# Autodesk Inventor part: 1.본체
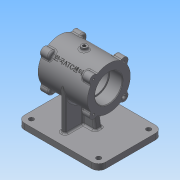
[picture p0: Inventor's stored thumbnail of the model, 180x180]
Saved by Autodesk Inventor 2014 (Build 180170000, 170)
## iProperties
Created: 2016-01
Part Number: 1.본체
Material: Generic
Document SubType Name: Modeling
Designer: Administrator
Density: 1 g/cm^3
Appearance: Default
Author: Administrator
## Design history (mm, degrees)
sketch "스케치1"
  geometry: L1 (-70, 55)-(70, 55); L2 (70, 55)-(70, -55); L3 (70, -55)-(-70, -55); L4 (-70, -55)-(-70, 55); L5 (-70, 55)-(70, -55); L6 (70, 55)-(-70, -55); 1 further point
  constraints: 12 end point, 2 midpoint, 2 parallel, 1 horizontal, 1 perpendicular
  dimensions: "d0" = 140 distance between parallel lines of L2 L4; "d1" = 110 distance between parallel lines of L3 L1
extrude "돌출1" new body sketch "스케치1" distance "d2" = 10; taper "d3" = 0 deg
node "작업 평면1"
sketch "스케치2"
  geometry: L1 (0, 110)-(0, 0) reference; C1 r 37 at (-80, 55); 2 further points
  constraints: 1 centre point, 1 horizontal alignment, 1 midpoint
  dimensions: "d5" = 80 distance from line of L1 C1.centre; "d6" = 74 diameter of C1
extrude "돌출2" join sketch "스케치2" stored distance "d7" = 85; taper "d8" = 0 deg
node "작업 평면2"
sketch "스케치3"
  geometry: L1 (80, -55)-(80, 55) reference; L2 (80, -55)-(70, -55) reference; L3 (70, 55)-(70, -55) reference; L4 (80, 55)-(70, 55) reference; L5 (0, -37)-(70, -37); L6 (0, 37)-(70, 37); A1 r 37 centre (0, 0) between (0, -37) and (0, 37) reference; 1 further point
  constraints: 4 end point, 2 horizontal, 2 point on circle, 2 point on line, 2 tangent
extrude "돌출3" join sketch "스케치3" stored distance "d10" = 8; taper "d11" = 0 deg
node "작업 평면3"
sketch "스케치4"
  geometry: L1 (-70, 0)-(70, 0) reference; L2 (-70, 0)-(-70, 10) reference; L3 (70, 10)-(-70, 10) reference; L4 (70, 0)-(70, 10) reference; L5 (14, 80)-(14, 80) reference; L6 (14, 80)-(6, 80) reference; L7 (6, 80)-(6, 80) reference; L8 (14, 80)-(6, 80) reference; L9 (52.5, 43)-(52.5, 117) reference; L10 (-32.5, 117)-(-32.5, 43) reference; L11 (-9.782, 42.948)-(-15, 10); L12 (29.782, 42.948)-(35, 10); L13 (6, 10)-(14, 10) reference; L14 (6, 80)-(6, 10) reference; L15 (14, 80)-(6, 80) reference; L16 (14, 10)-(14, 80) reference; L17 (-9.782, 42.948)-(-6.179, 65.693); L18 (29.782, 42.948)-(26.179, 65.693); L19 (26.179, 65.693)-(-6.179, 65.693); 3 further points
  constraints: 10 end point, 2 collinear, 2 midpoint, 2 point on line, 1 equal length, 1 horizontal, 1 vertical alignment
  dimensions: "d13" = 99 deg angle of L3 L11; "d14" = 99 deg angle of L3 L12; "d18" = 25 distance of point (10, 10) L11.end; "d19" = 25 distance of point (10, 10) L12.end; "d20" = 32.35825 distance of L18.end L17.end
extrude "돌출4" join sketch "스케치4" stored distance "d21" = 12; taper "d22" = 0 deg
node "작업 평면4"
sketch "스케치6"
  geometry: C1 r 37 at (0, 0) reference; C2 r 23.5 at (0, 0); 1 further point
  constraints: 1 centre point, 1 coincident
  dimensions: "d24" = 47 diameter of C2
extrude "돌출5" cut sketch "스케치6" distance "d25" = 22; taper "d26" = 0 deg
sketch "스케치7"
  geometry: C1 r 21 at (0, 0); C2 r 37 at (0, 0) reference; 1 further point
  constraints: 1 centre point, 1 coincident, 1 horizontal alignment
  dimensions: "d27" = 42 diameter of C1
extrude "돌출6" cut sketch "스케치7" distance "d28" = 41; taper "d29" = 0 deg
node "작업 평면5"
sketch "스케치8"
  geometry: C1 r 37 at (0, 0) reference; C2 r 23.5 at (0, 0); 1 further point
  constraints: 1 centre point, 1 coincident
  dimensions: "d31" = 47 diameter of C2
extrude "돌출7" cut sketch "스케치8" distance "d32" = 22; taper "d33" = 0 deg
node "작업 평면6"
sketch "스케치9"
  geometry: L1 (32.5, -37)-(32.5, 37) reference; L2 (-52.5, 37)-(32.5, 37) reference; L3 (-52.5, 37)-(-52.5, -37) reference; L4 (-52.5, -37)-(32.5, -37) reference; C1 r 5 at (-10, 0); 2 further points
  constraints: 1 centre point, 1 horizontal alignment, 1 midpoint
  dimensions: "d35" = 42.5 distance from line of C1.centre L3; "d36" = 10 diameter of C1
extrude "돌출8" join sketch "스케치9" stored distance "d37" = 22; taper "d38" = 0 deg
sketch "스케치10"
  geometry: L1 (-52.5, 37)-(-52.5, -37) reference; 1 further point
hole "구멍1" diameter "d42" = 5.188; stored, may be unused: countersink angle "d46" = 90 deg, drill point angle "d48" = 0 deg; dims "d40" = 10, "d41" = 10, "d43" = 10, "d44" = 10, "d45" = 2, "d47" = 8
sketch "스케치11"
  geometry: C1 r 23.5 at (0, 0) reference; C2 r 7 at (-26.163, -26.163); C3 r 7 at (-26.163, 26.163); C4 r 7 at (26.163, -26.163); C5 r 7 at (26.163, 26.163); A1 r 37 centre (0, 0) between (-26.163, -26.163) and (-26.163, 26.163) reference; A2 r 37 centre (0, 0) between (-26.163, -26.163) and (-26.163, 26.163); 2 further points
  constraints: 8 point on circle, 5 centre point, 4 equal radius, 2 coincident, 2 horizontal alignment, 2 vertical alignment
  dimensions: "d49" = 7 radius of C3; "d50" = 90 deg dimension on C1.centre C3.centre C2.centre
extrude "돌출9" join sketch "스케치11" distance "d51" = 15; taper "d52" = 0 deg
sketch "스케치12"
  geometry: A1 r 7 centre (-106.163, 81.163) between (-100.767, 85.622) and (-110.622, 75.767) reference; A2 r 7 centre (-106.163, 28.837) between (-110.622, 34.233) and (-100.767, 24.378) reference; A3 r 7 centre (-53.837, 28.837) between (-59.233, 24.378) and (-49.378, 34.233) reference; A4 r 7 centre (-53.837, 81.163) between (-49.378, 75.767) and (-59.233, 85.622) reference; 5 further points
  constraints: 4 coincident
hole "구멍2" sketch "스케치12" at (-106.163, 81.163), (-106.163, 28.837), (-53.837, 28.837), (-53.837, 81.163) diameter "d53" = 3.242; stored, may be unused: countersink angle "d57" = 90 deg, drill point angle "d59" = 118 deg; dims "d54" = 9, "d55" = 10, "d56" = 2, "d58" = 11
node "작업 평면7"
sketch "스케치13"
  geometry: L1 (70, 55)-(-70, 55) reference; L2 (-70, 55)-(-70, -55) reference; L3 (-58, 43)-(58, 43); L4 (58, 43)-(58, -43); L5 (58, -43)-(-58, -43); L6 (-58, -43)-(-58, 43); 5 further points
  constraints: 8 end point, 4 coincident, 2 parallel, 1 horizontal, 1 perpendicular
  dimensions: "d61" = 86 distance between parallel lines of L5 L3; "d62" = 116 distance between parallel lines of L4 L6; "d63" = 12 distance from line of point (-58, 43) L1; "d64" = 12 distance from line of L2 point (-58, 43)
hole "구멍3" sketch "스케치13" at (-58, 43), (58, 43), (-58, -43), (58, -43) diameter "d65" = 8; stored, may be unused: countersink angle "d69" = 90 deg, drill point angle "d71" = 118 deg; dims "d66" = 9, "d67" = 10, "d68" = 2, "d70" = 11
sketch "스케치14"
  geometry: L1 (70, 55)-(-70, 55) reference; L2 (70, -55)-(70, 55) reference; L3 (-35, 40)-(38.226, 40); L4 (55, 23.226)-(55, -23.226); L5 (38.226, -40)-(-38.226, -40); L6 (-55, -23.226)-(-55, 23.226); L7 (-55, 40)-(55, -40); L8 (55, 40)-(-55, -40); C1 r 4 at (58, -43) reference; C2 r 4 at (58, 43) reference; C3 r 4 at (-58, 43) reference; C4 r 4 at (-58, -43) reference; A1 r 20 centre (-58, -43) between (-38.226, -40) and (-55, -23.226); A2 r 20 centre (58, -43) between (55, -23.226) and (38.226, -40); A3 r 20 centre (58, 43) between (38.226, 40) and (55, 23.226); A4 r 20 centre (-58, 43) between (-55, 23.226) and (-38.278, 39.677); A5 r 16.774 centre (38.226, 23.226) between (55, 23.226) and (55, 23.226); A6 r 16.774 centre (38.226, 23.226) between (38.226, 40) and (38.226, 40); A7 r 16.774 centre (38.226, -23.226) between (38.226, -40) and (38.226, -40); A8 r 16.774 centre (38.226, -23.226) between (55, -23.226) and (55, -23.226); A9 r 16.774 centre (-35, 23.226) between (-35, 40) and (-38.278, 39.677); A10 r 20 centre (-35, 23.226) between (-55, 23.226) and (-55, 23.226); A11 r 16.774 centre (-38.226, -23.226) between (-55, -23.226) and (-55, -23.226); A12 r 16.774 centre (-38.226, -23.226) between (-38.226, -40) and (-38.226, -40); 8 further points
  constraints: 37 point on circle, 12 centre point, 12 end point, 9 point on line, 8 tangent, 4 coincident, 3 equal radius, 2 midpoint, 2 parallel, 1 horizontal, 1 perpendicular
  dimensions: "d73" = 15 distance between parallel lines of L4 L2; "d74" = 15 distance between parallel lines of L1 L3; "d77" = 20 radius of A4
extrude "돌출10" cut sketch "스케치14" distance "d78" = 5; taper "d79" = 0 deg
sketch "스케치15"
  geometry: L1 (-80, 55)-(-106.163, 28.837); L2 (-106.163, 28.837)-(-136.752, -1.752); C1 r 1.621 at (-53.837, 28.837) reference; C2 r 1.621 at (-106.163, 81.163) reference; C3 r 1.621 at (-106.163, 28.837) reference; C4 r 1.621 at (-53.837, 81.163) reference; C5 r 23.5 at (-80, 55) reference; A1 r 37 centre (-80, 55) between (-59.233, 85.622) and (-100.767, 85.622) reference; A2 r 7 centre (-106.163, 81.163) between (-100.767, 85.622) and (-110.622, 75.767) reference; A3 r 37 centre (-80, 55) between (-110.622, 75.767) and (-110.622, 34.233) reference; A4 r 7 centre (-106.163, 28.837) between (-110.622, 34.233) and (-100.767, 24.378) reference; A5 r 37 centre (-80, 55) between (-100.767, 24.378) and (-59.233, 24.378) reference; A6 r 7 centre (-53.837, 28.837) between (-59.233, 24.378) and (-49.378, 34.233) reference; A7 r 37 centre (-80, 55) between (-49.378, 34.233) and (-49.378, 75.767) reference; A8 r 7 centre (-53.837, 81.163) between (-49.378, 75.767) and (-59.233, 85.622) reference; 3 further points
  constraints: 4 end point, 1 coincident, 1 collinear, 1 point on circle
node "작업 평면9"
sketch "스케치16"
  geometry: L1 (0, 7)-(0, -7) reference; L2 (-46.5, 26.163)-(-38.5, 26.163) reference; 8 further points
  constraints: 2 horizontal alignment, 2 midpoint, 2 vertical alignment, 1 other
fillet "모깎기1" dims "d80" = 12, "d82" = 0.3
fillet "모깎기2" dims "d81" = 1
fillet "모깎기3" dims "d83" = 3
fillet "모깎기4" dims "d84" = 3
feature "엠보싱1" dims "d85" = 0.5, "d86" = 0
fillet "모깎기5" dims "d87" = 3
fillet "모깎기6" dims "d88" = 3
fillet "모깎기7" dims "d89" = 3
chamfer "모따기1" distance "d90" = 1; stored, may be unused: second distance "d91" = 2, angle "d92" = 45 deg
node "솔리드1"
mirror "대칭1"
node "투영된 루프1"
node "투영된 루프2"
node "투영된 루프3"
node "투영된 루프4"
node "투영된 루프5"
other parameters: "d9" = -42.5, "d12" = 0, "d23" = -22, "d30" = -22, "d34" = 122, "d60" = -42.5
